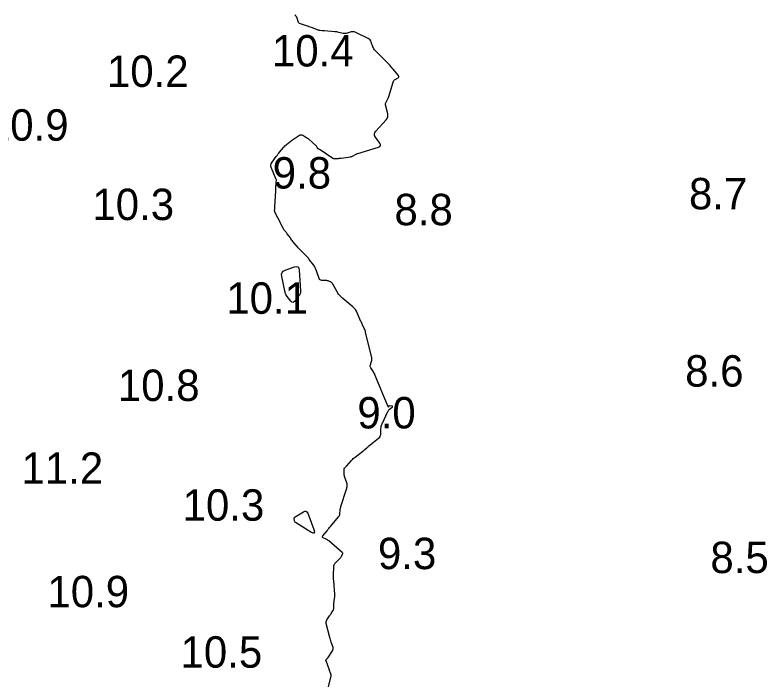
# Model space of a CAD drawing. Extents: x 1023796 to 1112670, y 656573 to 837340.
# Drawn here: x 1100652.7 to 1100772.5, y 688658.2 to 688764.2 of the extents above; entities that cross this region are included whole.
import ezdxf

# ---------------------------------------------------------------- set-up
doc = ezdxf.new("R2010")
doc.units = 0
doc.layers.add('V-CHAN-CONT-10FT', color=7, linetype='Continuous')
doc.layers.add('V-TOPO-SOUN', color=7, linetype='Continuous')

msp = doc.modelspace()

# ---------------------------------------------------------------- linework, layer by layer
at = {"layer": 'V-CHAN-CONT-10FT'}
msp.add_lwpolyline([(1100702.65, 688657.29), (1100703.03, 688659.03), (1100703.04, 688659.1), (1100703.04, 688659.18), (1100703.02, 688659.25), (1100703, 688659.32), (1100702.89, 688659.61), (1100702.86, 688659.69), (1100702.83, 688659.76), (1100702.81, 688659.83), (1100702.78, 688659.91), (1100702.23, 688661.42), (1100702.22, 688661.48), (1100702.22, 688661.52), (1100702.24, 688661.57), (1100702.27, 688661.61), (1100702.42, 688661.77), (1100702.46, 688661.81), (1100702.5, 688661.86), (1100702.53, 688661.9), (1100702.56, 688661.95), (1100703.25, 688663.01), (1100703.33, 688663.17), (1100703.37, 688663.34), (1100703.37, 688663.51), (1100703.32, 688663.69), (1100703.05, 688664.4), (1100702.99, 688664.58), (1100702.93, 688664.77), (1100702.87, 688664.95), (1100702.82, 688665.13), (1100702.26, 688667.33), (1100702.23, 688667.49), (1100702.24, 688667.64), (1100702.29, 688667.79), (1100702.36, 688667.93), (1100702.78, 688668.55), (1100702.84, 688668.65), (1100702.91, 688668.75), (1100702.98, 688668.84), (1100703.04, 688668.94), (1100703.34, 688669.36), (1100703.39, 688669.45), (1100703.42, 688669.54), (1100703.44, 688669.63), (1100703.45, 688669.73), (1100703.45, 688670.13), (1100703.45, 688670.23), (1100703.46, 688670.33), (1100703.47, 688670.42), (1100703.48, 688670.52), (1100703.59, 688671.35), (1100703.61, 688671.52), (1100703.62, 688671.69), (1100703.62, 688671.86), (1100703.61, 688672.03), (1100703.46, 688674.14), (1100703.44, 688674.4), (1100703.43, 688674.66), (1100703.43, 688674.92), (1100703.43, 688675.18), (1100703.45, 688676.34), (1100703.47, 688676.54), (1100703.53, 688676.71), (1100703.62, 688676.88), (1100703.74, 688677.03), (1100704.46, 688677.74), (1100704.52, 688677.81), (1100704.58, 688677.89), (1100704.63, 688677.96), (1100704.68, 688678.04), (1100704.86, 688678.37), (1100704.89, 688678.45), (1100704.89, 688678.53), (1100704.86, 688678.6), (1100704.81, 688678.66), (1100702.68, 688680.5), (1100702.58, 688680.58), (1100702.48, 688680.66), (1100702.37, 688680.72), (1100702.26, 688680.78), (1100701.8, 688680.99), (1100701.71, 688681.05), (1100701.67, 688681.12), (1100701.68, 688681.21), (1100701.73, 688681.3), (1100702.39, 688682.13), (1100702.52, 688682.3), (1100702.66, 688682.47), (1100702.8, 688682.64), (1100702.94, 688682.81), (1100704.24, 688684.33), (1100704.32, 688684.44), (1100704.38, 688684.57), (1100704.43, 688684.7), (1100704.45, 688684.84), (1100704.49, 688685.42), (1100704.51, 688685.56), (1100704.53, 688685.7), (1100704.57, 688685.84), (1100704.61, 688685.98), (1100705.5, 688688.73), (1100705.51, 688688.77), (1100705.52, 688688.8), (1100705.53, 688688.83), (1100705.54, 688688.87), (1100705.57, 688689.01), (1100705.57, 688689.04), (1100705.58, 688689.08), (1100705.58, 688689.12), (1100705.59, 688689.15), (1100705.6, 688689.49), (1100705.59, 688689.55), (1100705.59, 688689.62), (1100705.57, 688689.69), (1100705.55, 688689.75), (1100705.2, 688690.74), (1100705.16, 688690.86), (1100705.14, 688691), (1100705.12, 688691.13), (1100705.12, 688691.26), (1100705.13, 688691.97), (1100705.14, 688692.02), (1100705.15, 688692.07), (1100705.18, 688692.12), (1100705.22, 688692.16), (1100705.38, 688692.31), (1100705.42, 688692.35), (1100705.47, 688692.39), (1100705.5, 688692.43), (1100705.54, 688692.47), (1100706.29, 688693.31), (1100706.43, 688693.46), (1100706.57, 688693.6), (1100706.73, 688693.74), (1100706.89, 688693.86), (1100708.1, 688694.79), (1100708.18, 688694.86), (1100708.26, 688694.92), (1100708.34, 688694.98), (1100708.41, 688695.05), (1100708.71, 688695.31), (1100708.79, 688695.37), (1100708.86, 688695.44), (1100708.94, 688695.5), (1100709.02, 688695.56), (1100710.6, 688696.84), (1100710.74, 688696.98), (1100710.85, 688697.14), (1100710.91, 688697.32), (1100710.94, 688697.51), (1100710.98, 688698.34), (1100711, 688698.55), (1100711.03, 688698.75), (1100711.09, 688698.94), (1100711.17, 688699.13), (1100712.06, 688701.08), (1100712.11, 688701.18), (1100712.18, 688701.28), (1100712.26, 688701.38), (1100712.35, 688701.46), (1100712.79, 688701.82), (1100712.83, 688701.87), (1100712.84, 688701.91), (1100712.82, 688701.94), (1100712.75, 688701.95), (1100712.32, 688702.02), (1100712.29, 688702.02), (1100712.27, 688702.01), (1100712.25, 688701.99), (1100712.23, 688701.97), (1100712.18, 688701.85), (1100712.17, 688701.83), (1100712.16, 688701.82), (1100712.15, 688701.83), (1100712.13, 688701.85), (1100710.07, 688706.83), (1100710.04, 688706.88), (1100710.02, 688706.93), (1100710, 688706.98), (1100709.98, 688707.03), (1100709.88, 688707.22), (1100709.85, 688707.27), (1100709.83, 688707.32), (1100709.8, 688707.36), (1100709.77, 688707.41), (1100709.37, 688708.04), (1100709.31, 688708.16), (1100709.28, 688708.29), (1100709.28, 688708.41), (1100709.31, 688708.55), (1100709.49, 688709.1), (1100709.53, 688709.24), (1100709.54, 688709.38), (1100709.54, 688709.52), (1100709.51, 688709.66), (1100708.54, 688713.72), (1100708.5, 688713.88), (1100708.45, 688714.02), (1100708.4, 688714.17), (1100708.33, 688714.31), (1100708.05, 688714.88), (1100707.99, 688715.02), (1100707.92, 688715.16), (1100707.86, 688715.31), (1100707.79, 688715.45), (1100707.21, 688716.82), (1100707.08, 688717.08), (1100706.92, 688717.33), (1100706.73, 688717.55), (1100706.51, 688717.76), (1100704.92, 688719.09), (1100704.85, 688719.15), (1100704.78, 688719.21), (1100704.71, 688719.28), (1100704.64, 688719.34), (1100704.37, 688719.6), (1100704.3, 688719.67), (1100704.24, 688719.74), (1100704.19, 688719.81), (1100704.14, 688719.89), (1100703.32, 688721.4), (1100703.27, 688721.49), (1100703.2, 688721.56), (1100703.13, 688721.62), (1100703.04, 688721.68), (1100702.67, 688721.86), (1100702.58, 688721.9), (1100702.48, 688721.93), (1100702.38, 688721.95), (1100702.28, 688721.96), (1100701.56, 688721.97), (1100701.41, 688721.99), (1100701.3, 688722.05), (1100701.21, 688722.14), (1100701.15, 688722.27), (1100700.72, 688723.52), (1100700.62, 688723.76), (1100700.51, 688724), (1100700.38, 688724.22), (1100700.23, 688724.43), (1100699.57, 688725.31), (1100699.43, 688725.5), (1100699.28, 688725.68), (1100699.12, 688725.85), (1100698.95, 688726.02), (1100698.26, 688726.67), (1100698.1, 688726.83), (1100697.93, 688727), (1100697.78, 688727.18), (1100697.63, 688727.36), (1100696.97, 688728.18), (1100696.86, 688728.32), (1100696.76, 688728.45), (1100696.65, 688728.59), (1100696.55, 688728.73), (1100696.03, 688729.4), (1100695.98, 688729.48), (1100695.92, 688729.55), (1100695.87, 688729.62), (1100695.81, 688729.7), (1100695.59, 688729.99), (1100695.53, 688730.06), (1100695.48, 688730.14), (1100695.44, 688730.21), (1100695.39, 688730.29), (1100695.2, 688730.67), (1100695.16, 688730.76), (1100695.11, 688730.86), (1100695.06, 688730.95), (1100695.02, 688731.04), (1100694.1, 688732.86), (1100694.08, 688732.92), (1100694.06, 688732.98), (1100694.05, 688733.04), (1100694.05, 688733.1), (1100694.06, 688733.36), (1100694.07, 688733.42), (1100694.07, 688733.49), (1100694.07, 688733.55), (1100694.08, 688733.62), (1100694.23, 688736.25), (1100694.24, 688736.38), (1100694.25, 688736.52), (1100694.25, 688736.65), (1100694.26, 688736.78), (1100694.29, 688737.49), (1100694.3, 688737.54), (1100694.3, 688737.58), (1100694.3, 688737.63), (1100694.31, 688737.68), (1100694.33, 688737.87), (1100694.33, 688737.92), (1100694.33, 688737.96), (1100694.32, 688738.01), (1100694.3, 688738.05), (1100693.53, 688739.87), (1100693.46, 688740.11), (1100693.46, 688740.34), (1100693.52, 688740.56), (1100693.64, 688740.78), (1100694.3, 688741.7), (1100694.43, 688741.88), (1100694.56, 688742.05), (1100694.7, 688742.22), (1100694.83, 688742.39), (1100695.45, 688743.13), (1100695.56, 688743.26), (1100695.68, 688743.38), (1100695.81, 688743.5), (1100695.94, 688743.61), (1100696.48, 688744.05), (1100696.61, 688744.16), (1100696.75, 688744.26), (1100696.89, 688744.36), (1100697.04, 688744.46), (1100698.02, 688745.08), (1100698.14, 688745.14), (1100698.27, 688745.16), (1100698.39, 688745.14), (1100698.52, 688745.09), (1100699.02, 688744.79), (1100699.14, 688744.72), (1100699.26, 688744.64), (1100699.37, 688744.55), (1100699.48, 688744.45), (1100700.65, 688743.41), (1100700.68, 688743.38), (1100700.71, 688743.34), (1100700.73, 688743.3), (1100700.75, 688743.26), (1100700.82, 688743.08), (1100700.84, 688743.04), (1100700.86, 688743.01), (1100700.9, 688742.98), (1100700.94, 688742.96), (1100701.12, 688742.89), (1100701.17, 688742.87), (1100701.21, 688742.85), (1100701.25, 688742.83), (1100701.29, 688742.8), (1100703.34, 688741.46), (1100703.44, 688741.4), (1100703.54, 688741.37), (1100703.65, 688741.35), (1100703.76, 688741.36), (1100704.21, 688741.4), (1100704.33, 688741.42), (1100704.44, 688741.43), (1100704.55, 688741.44), (1100704.67, 688741.46), (1100706.15, 688741.66), (1100706.26, 688741.68), (1100706.36, 688741.71), (1100706.45, 688741.75), (1100706.55, 688741.8), (1100706.92, 688742.02), (1100707.01, 688742.08), (1100707.11, 688742.12), (1100707.21, 688742.16), (1100707.31, 688742.2), (1100710.59, 688743.19), (1100710.82, 688743.3), (1100710.93, 688743.44), (1100710.92, 688743.62), (1100710.8, 688743.84), (1100710.1, 688744.8), (1100709.97, 688745.04), (1100709.94, 688745.27), (1100709.99, 688745.5), (1100710.15, 688745.72), (1100711.8, 688747.55), (1100711.96, 688747.77), (1100712.05, 688748), (1100712.08, 688748.25), (1100712.05, 688748.52), (1100711.72, 688749.92), (1100711.71, 688750.04), (1100711.71, 688750.15), (1100711.74, 688750.26), (1100711.79, 688750.37), (1100712.04, 688750.79), (1100712.1, 688750.9), (1100712.15, 688751.01), (1100712.2, 688751.12), (1100712.23, 688751.24), (1100712.91, 688753.56), (1100712.96, 688753.68), (1100713.03, 688753.79), (1100713.12, 688753.89), (1100713.23, 688753.97), (1100713.71, 688754.25), (1100713.81, 688754.32), (1100713.85, 688754.41), (1100713.84, 688754.5), (1100713.77, 688754.6), (1100712.91, 688755.63), (1100712.73, 688755.84), (1100712.55, 688756.04), (1100712.37, 688756.24), (1100712.18, 688756.43), (1100710.1, 688758.53), (1100709.97, 688758.68), (1100709.86, 688758.83), (1100709.77, 688759), (1100709.7, 688759.18), (1100709.43, 688759.92), (1100709.35, 688760.1), (1100709.24, 688760.25), (1100709.11, 688760.37), (1100708.95, 688760.47), (1100706.89, 688761.48), (1100706.74, 688761.54), (1100706.58, 688761.57), (1100706.42, 688761.57), (1100706.26, 688761.53), (1100705.59, 688761.33), (1100705.43, 688761.29), (1100705.27, 688761.27), (1100705.1, 688761.27), (1100704.94, 688761.3), (1100704.28, 688761.46), (1100704.11, 688761.5), (1100703.94, 688761.53), (1100703.78, 688761.55), (1100703.61, 688761.57), (1100702.01, 688761.7), (1100701.63, 688761.73), (1100701.25, 688761.76), (1100701.15, 688761.77), (1100701.06, 688761.79), (1100700.97, 688761.82), (1100700.88, 688761.85), (1100699.9, 688762.22), (1100699.71, 688762.29), (1100699.51, 688762.36), (1100699.32, 688762.43), (1100699.12, 688762.49), (1100698.16, 688762.82), (1100698.03, 688762.87), (1100697.93, 688762.95), (1100697.85, 688763.06), (1100697.79, 688763.19), (1100697.61, 688763.74), (1100697.56, 688763.87), (1100697.49, 688764), (1100697.41, 688764.12), (1100697.32, 688764.23)], dxfattribs=at)
for points in [[(1100695.68, 688720.19), (1100695.66, 688720.24), (1100695.65, 688720.3), (1100695.17, 688722.62), (1100695.14, 688722.97), (1100695.23, 688723.25), (1100695.43, 688723.47), (1100695.74, 688723.63), (1100697.2, 688724.12), (1100697.52, 688724.18), (1100697.76, 688724.12), (1100697.91, 688723.92), (1100697.98, 688723.6), (1100698.16, 688720.32), (1100698.16, 688720.08), (1100698.11, 688719.85), (1100698.01, 688719.64), (1100697.87, 688719.44), (1100697.21, 688718.64), (1100697.06, 688718.51), (1100696.92, 688718.47), (1100696.78, 688718.52), (1100696.65, 688718.66), (1100695.91, 688719.64), (1100695.88, 688719.69), (1100695.85, 688719.74), (1100695.82, 688719.8), (1100695.8, 688719.85), (1100695.72, 688720.07), (1100695.7, 688720.13)], [(1100699.03, 688685.23), (1100699.19, 688685.12), (1100699.31, 688684.9), (1100700.3, 688682.33), (1100700.41, 688681.95), (1100700.36, 688681.76), (1100700.16, 688681.75), (1100699.81, 688681.92), (1100697.38, 688683.42), (1100697.31, 688683.48), (1100697.25, 688683.54), (1100697.22, 688683.62), (1100697.2, 688683.71), (1100697.18, 688684.08), (1100697.18, 688684.16), (1100697.21, 688684.24), (1100697.25, 688684.3), (1100697.32, 688684.36), (1100698.62, 688685.14), (1100698.84, 688685.24)]]:
    msp.add_lwpolyline(points, close=True, dxfattribs=at)

# ---------------------------------------------------------------- texts
at = {"layer": 'V-TOPO-SOUN'}
for s, p in [('10.4 ', (1100693.62, 688756.03)), ('10.2 ', (1100667.34, 688752.78)), ('10.9 ', (1100648.22, 688744.22)), ('9.8', (1100693.74, 688736.6)), ('8.7', (1100760.04, 688733.29)), ('10.3 ', (1100665.02, 688731.58)), ('8.8', (1100713.13, 688730.76)), ('10.1 ', (1100686.35, 688716.66)), ('8.6', (1100759.43, 688705.07)), ('10.8 ', (1100669.08, 688702.78)), ('9.0', (1100707.22, 688698.41)), ('11.2 ', (1100653.73, 688689.59)), ('10.3 ', (1100679.39, 688683.72)), ('9.3', (1100710.5, 688676.01)), ('8.5', (1100763.45, 688675.38)), ('10.9 ', (1100657.86, 688669.94)), ('10.5 ', (1100679.06, 688660.32))]:
    msp.add_text(s, height=5, dxfattribs=at).set_placement(p)

doc.saveas('drawing.dxf')
